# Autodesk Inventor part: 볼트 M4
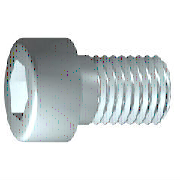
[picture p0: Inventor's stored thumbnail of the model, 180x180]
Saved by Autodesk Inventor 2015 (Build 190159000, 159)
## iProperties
IsCustomPart: 1
Created: 2012-02
Part Number: 볼트 M4
Material: 강철, 연강
Description: 6각머리 태핑 나사
Document SubType Name: Modeling
Standard: KS B 1003
Designer: mduedu
Standards Organization: KS
Language: ko-KR
Size Designation: M 4 x 10
Categories: <MemberInstance><Categories><Category DisplayName="조임쇠" InternalName="e4da775c-781d-43d5-af7c-5136215cf5a6" Mnemonic="FSTN"><Category DisplayName="볼트" InternalN
Density: 1 g/cm^3
Appearance: 강철
Author: mduedu
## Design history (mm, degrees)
sketch "스케치1"
  geometry: L1 (-1, 0)-(10, 0); L2 (10, 0)-(10, 2); L3 (10, 2)-(1.75, 2); L4 (1.75, 2)-(1.32, 2); L5 (1.32, 2)-(0, 2); L6 (0, 2)-(0, 3.5); L7 (0, 3.5)-(-4, 3.5); L8 (-4, 3.5)-(-4, 1.732); L9 (-4, 1.732)-(-2, 1.732); L10 (-2, 1.732)-(-1, 0); L11 (-6.8, 0)-(12.8, 0) reference; L12 (0, -0.7)-(0, 4.2) reference; L13 (1.75, 2)-(0, 2)
  constraints: 22 end point, 6 parallel, 2 collinear, 2 perpendicular, 1 horizontal, 1 point on line
  dimensions: "d1" = 8.25 distance from line of L3.end L2 (= GEL); "d2" = 0.42952 distance of L4.end L3.end (computed from GAL); "d3" = 4 distance between parallel lines of L8 L6 (= KOH); "d4" = 2 distance of L8.end L9.end (= INTI); "d5" = 60 deg angle of L10 L1; "d6" = 4 diameter of L3 L1 (= GD); "d7" = 4 diameter of L5 L1 (= BDM); "d8" = 3.4641 diameter of L9 L1 (= 1.1547 x SW); "d9" = 7 diameter of L7 L1 (= KOD); "d26" = 10 distance between parallel lines of L12 L2 (= NLG)
revolve "본체" sketch "스케치1" stored, may be unused: angle "d10" = 90 deg
sketch "스케치2"
  geometry: L1 (0, -4.9)-(0, 4.9) reference; L2 (-4.9, 0)-(4.9, 0) reference; L3 (1.732, 0)-(0.866, -1.5); L4 (0.866, -1.5)-(-0.866, -1.5); L5 (-0.866, -1.5)-(-1.732, 0); L6 (-1.732, 0)-(-0.866, 1.5); L7 (-0.866, 1.5)-(0.866, 1.5); L8 (0.866, 1.5)-(1.732, 0); 2 further points
  constraints: 12 end point, 1 coincident, 1 horizontal alignment, 1 point on line, 12 other
extrude "슬롯" join sketch "스케치2" stored distance "d11" = 10; taper "d12" = 0 deg
workplane "Work Plane1"
fillet "Fillet2" dims "d30" = 0.1 (= R)
body "Solid1"
fillet "모깎기1" dims "d17" = 0.4 (= RR)
feature "스레드" dims "d13" = 8.25 (= GEL), "d14" = 0
chamfer "모따기1" distance "d15" = 0.42941 (= -0.5 x SPD + 0.5 x GD); stored, may be unused: second distance "d16" = 0.42941 (= GUL), angle "d27" = 45 deg
other parameters: "GD" = 4 (= NND) [user parameter; used in 2 equation terms], "NLG" = 10 [user parameter; used in 1 equation term], "GEL" = 8.25 [user parameter; used in 2 equation terms], "KOD" = 7 [user parameter; used in 1 equation term], "KOH" = 4 [user parameter; used in 1 equation term], "INTI" = 2 [user parameter; used in 1 equation term], "GAL" = 0.42941 (= 0.61345 x PTC) [user parameter; used in 1 equation term], "GUL" = 0.42941 (= 0.61345 x PTC) [user parameter; used in 1 equation term], "BDM" = 4 (= NND) [user parameter; used in 1 equation term], "SW" = 3 [user parameter; used in 2 equation terms], "RR" = 0.4 [user parameter; used in 1 equation term], "SPD" = 3.14117 (= NND - 1.2269 x PTC) [user parameter; used in 1 equation term], "d19" = 0, "d28" = 0, "d29" = 0, "R" = 0.1 [user parameter; used in 1 equation term], "PHH" = 0.2 [user parameter], "GD1" = 3.14117 (= THREADDIA - 1.2269 x PTC) [user parameter], "THREADDIA" = 4 [user parameter; used in 1 equation term], "FAWI" = 45 deg [user parameter], "TPU" = 14.28571 (computed from PTC) [user parameter], "PTC" = 0.7 [user parameter; used in 5 equation terms], "NND" = 4 [user parameter; used in 3 equation terms], "TOA" = 30 deg [user parameter], "E0" = 3.465 (= 1.155 x SW) [user parameter]
